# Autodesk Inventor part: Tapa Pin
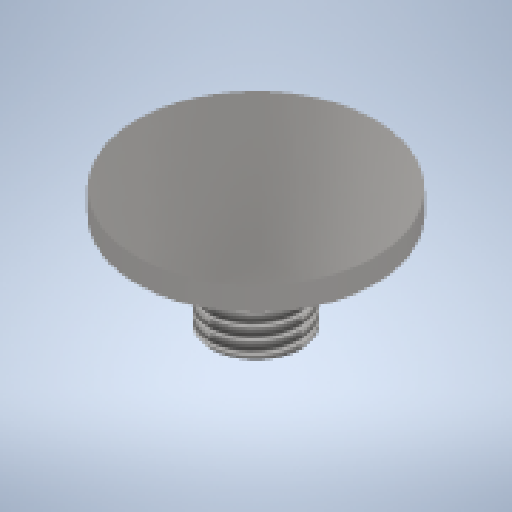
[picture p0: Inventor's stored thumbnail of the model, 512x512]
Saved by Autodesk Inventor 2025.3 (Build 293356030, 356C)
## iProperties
Created: 2025-10
Part Number: Tapa Pin
Material: Acero inoxidable
Document SubType Name: Modeling
Designer: Asus
Density: 8 g/cm^3
Appearance: Semipulido
Author: Asus
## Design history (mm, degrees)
sketch "Boceto1"
  geometry: C1 r 25.4 at (0, 0); 1 further point
  constraints: 1 centre point, 1 coincident
  dimensions: "d0" = 50.8 diameter of C1
extrude "Extrusión1" new body sketch "Boceto1" distance "d1" = 5; taper "d2" = 0 deg
sketch "Boceto2"
  geometry: C1 r 9.525 at (0, 0); 1 further point
  constraints: 1 centre point, 1 coincident
  dimensions: "d3" = 19.05 diameter of C1
extrude "Extrusión2" join sketch "Boceto2" distance "d4" = 20; taper "d5" = 0 deg
feature "Rosca1" dims "d13" = 100, "d14" = 0
node "Sólido1"
